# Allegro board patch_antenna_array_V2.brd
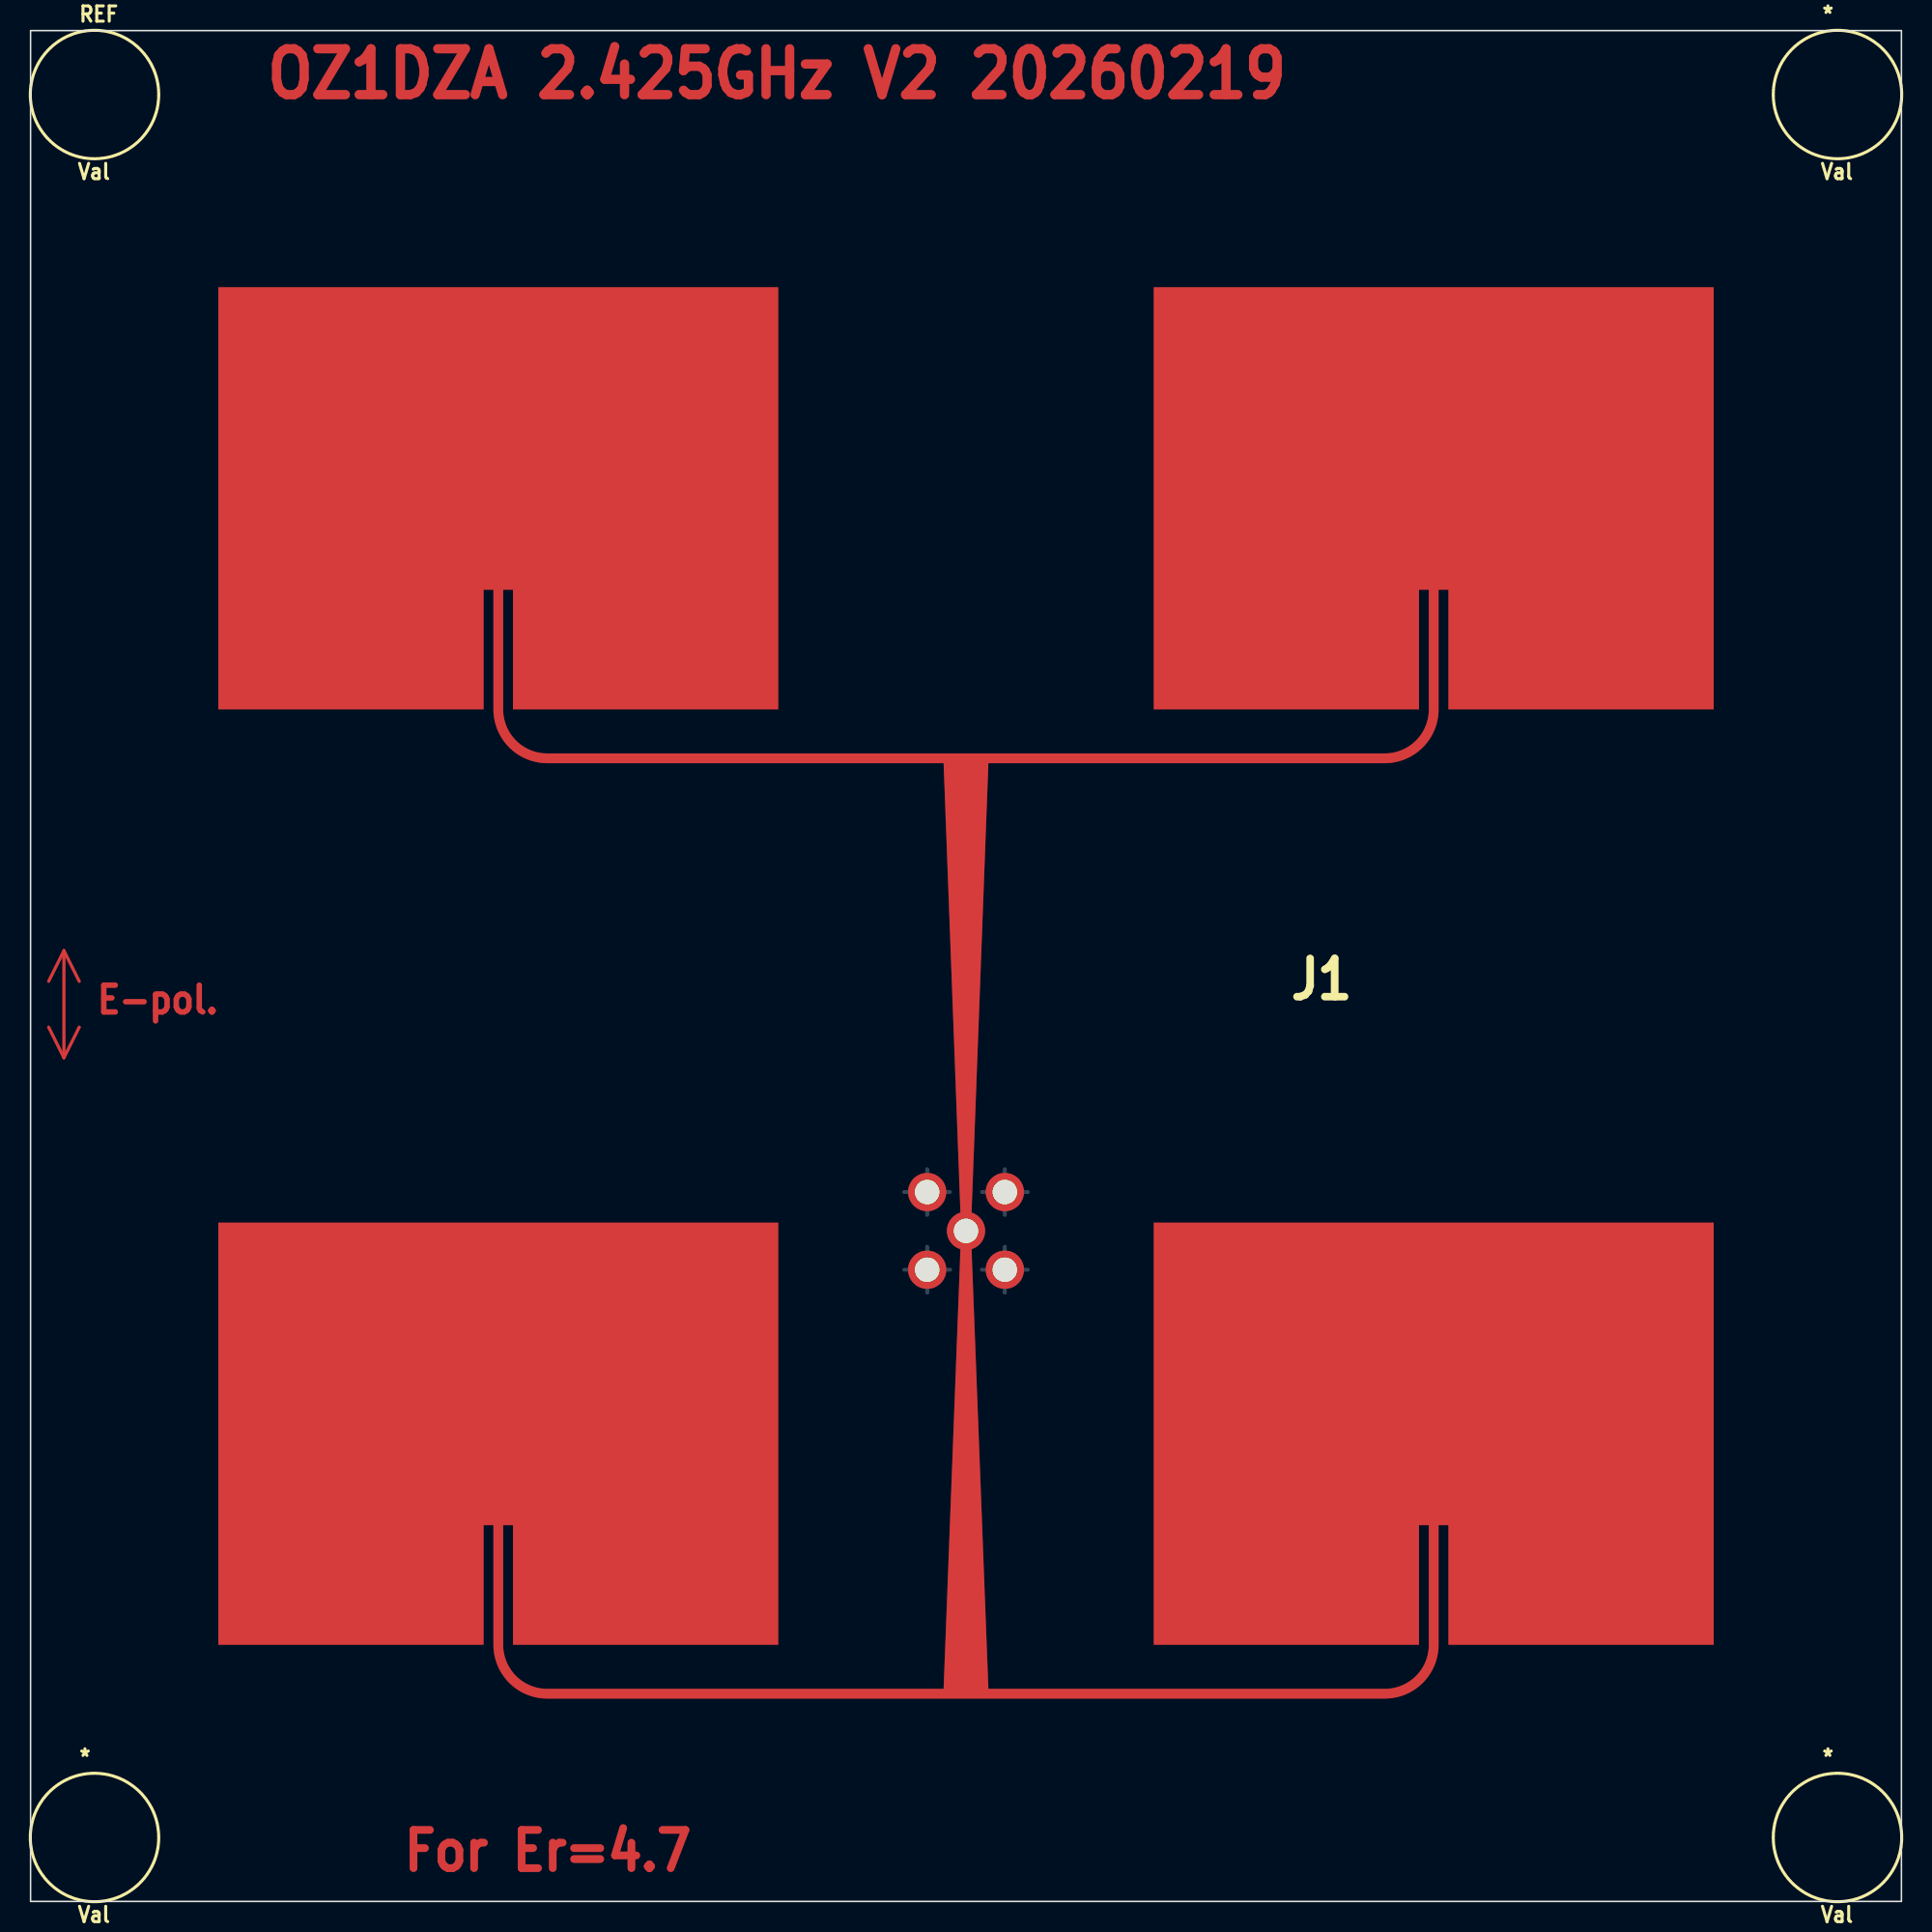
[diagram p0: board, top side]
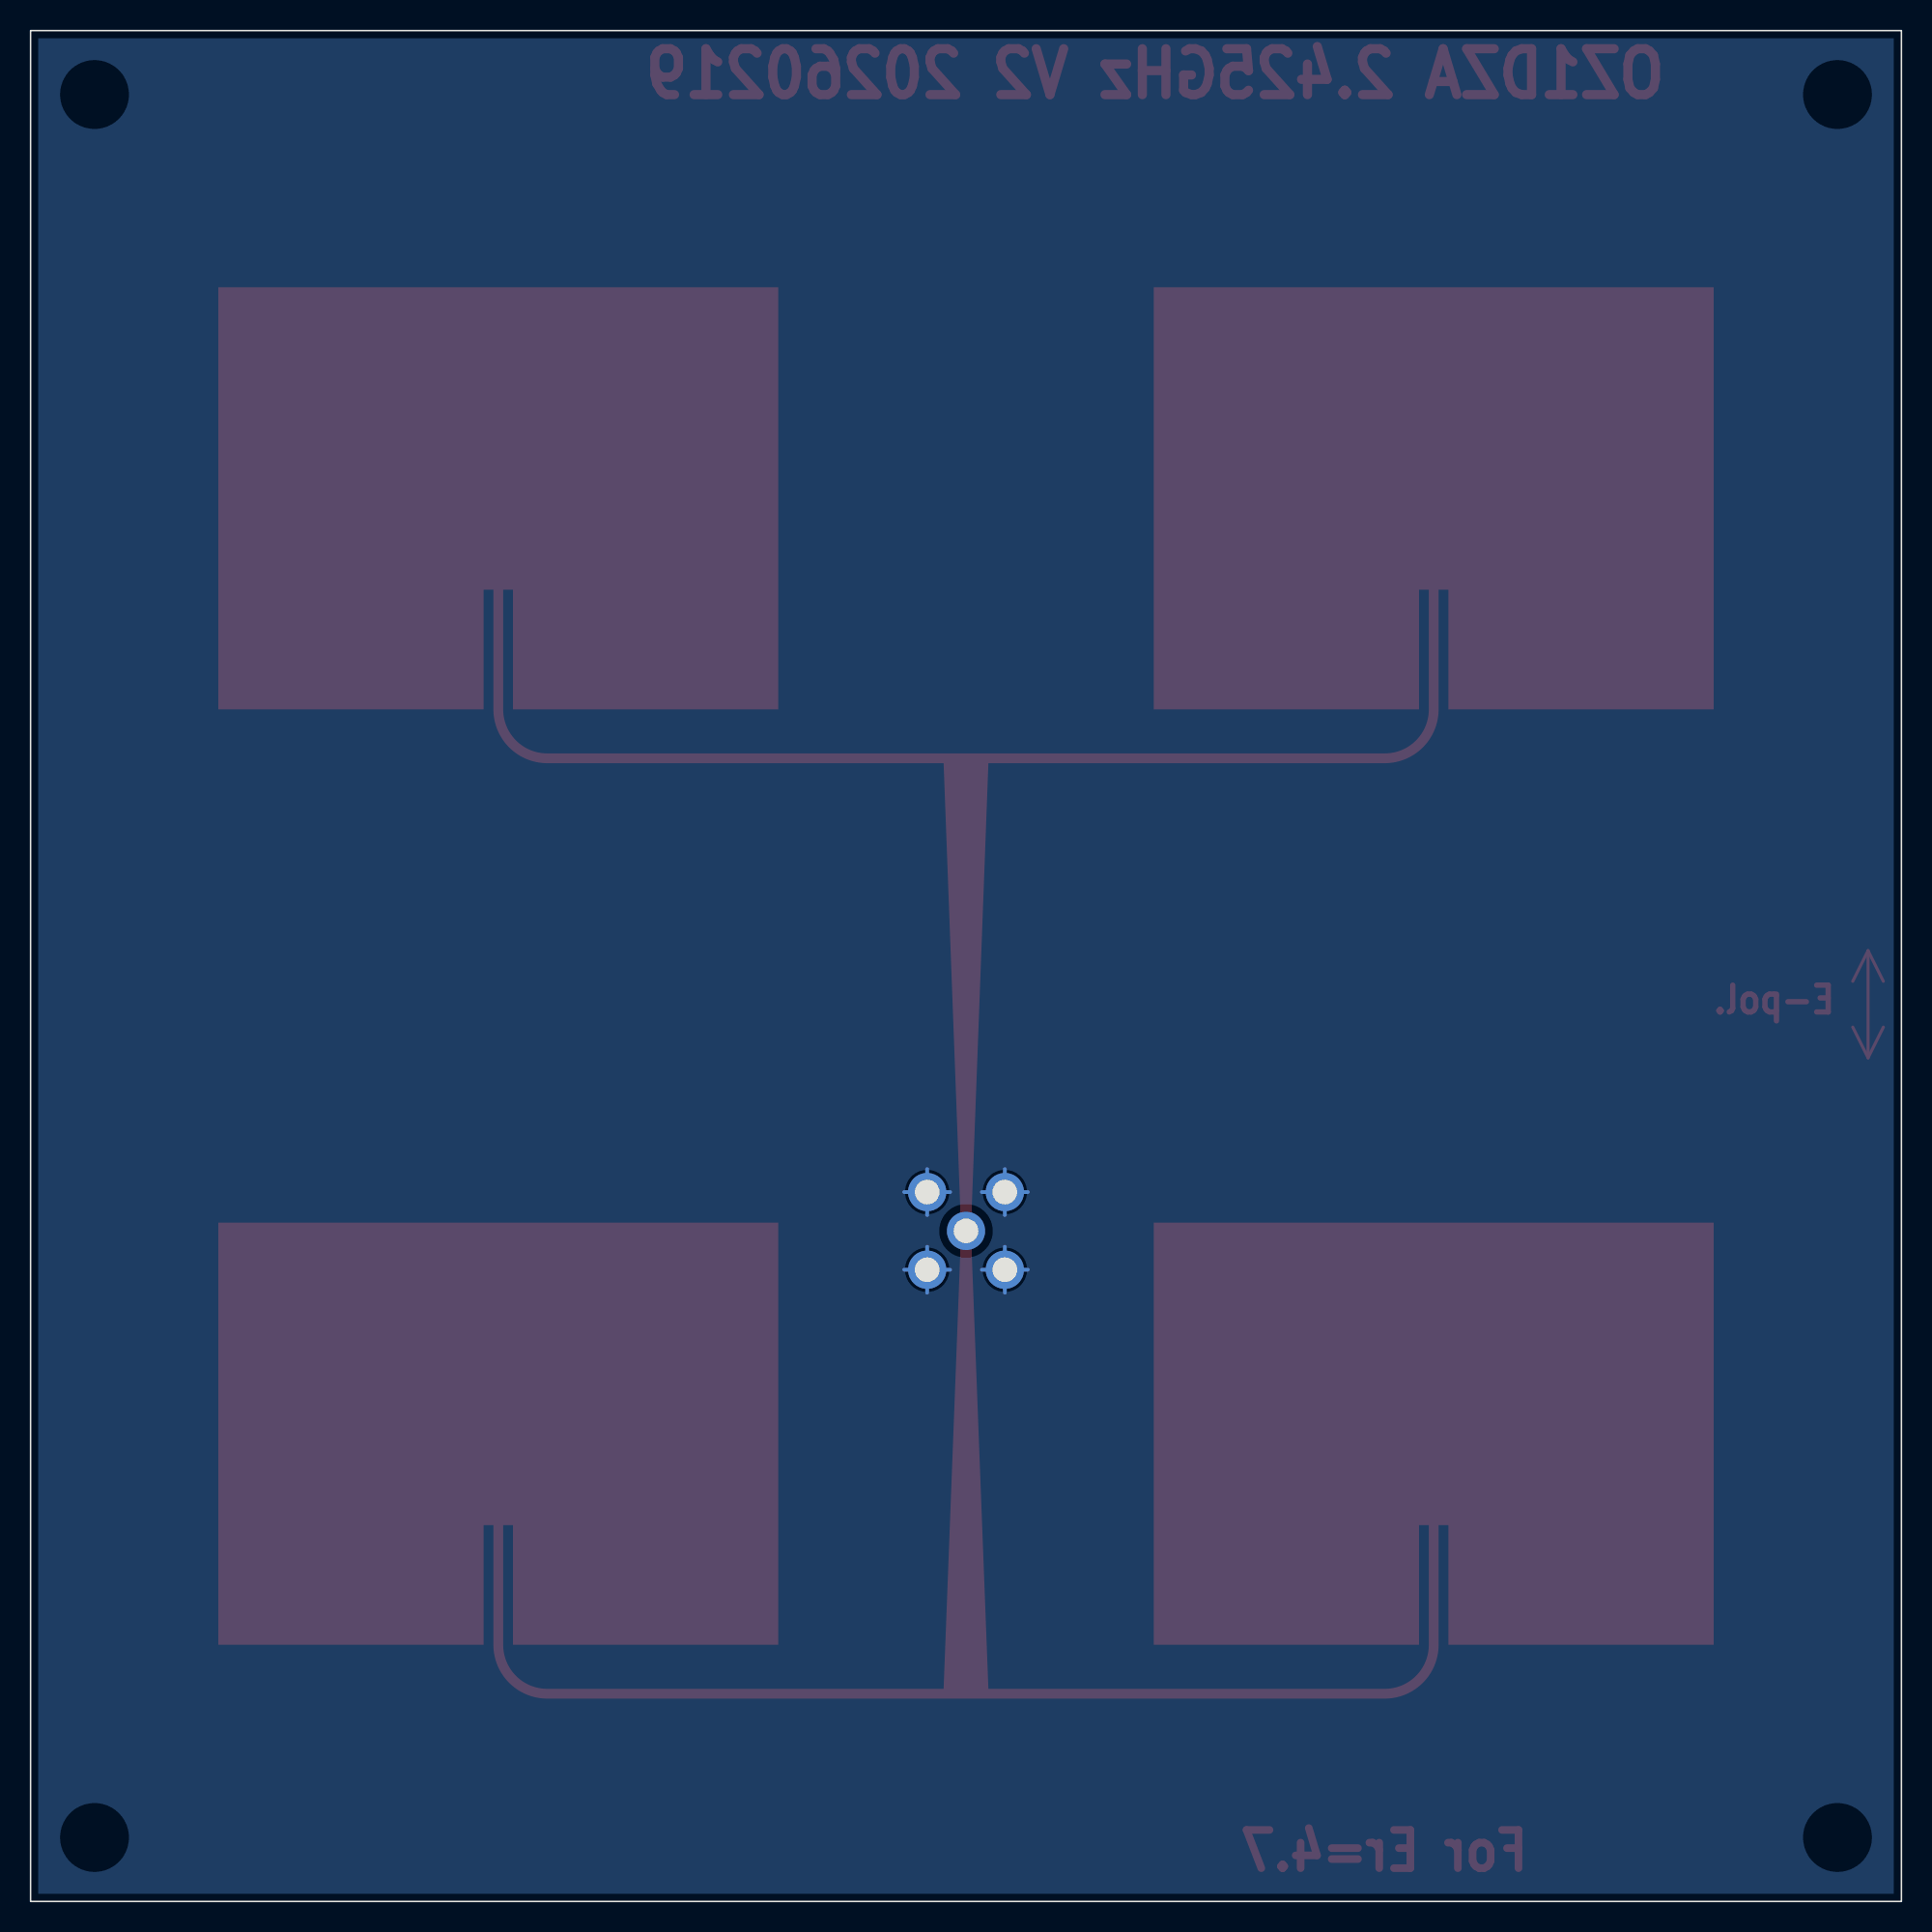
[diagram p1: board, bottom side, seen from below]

Outline 122.36 x 122.36 mm; copper layers: TOP, BOTTOM. Coordinates in mm from the lower left corner of the outline.
Outline path: rectangle 0,0 122.36,122.36

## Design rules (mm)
constraint set DEFAULT: min track width 0.3

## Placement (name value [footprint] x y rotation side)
J1  patch_antenna_array  [PATCH_ANTENNA_ARRAY]  61.18 61.18 0 top
NOREF  -  [#2]  0 0 0 top
NOREF#2  -  [#2]  122.36 0 90 top
REF  Val  [unnamed]  4.18 118.18 0 top
UNK*  Val  [unnamed]  118.18 118.18 0 top
UNK*#2  Val  [unnamed]  4.18 4.18 0 top
UNK*#3  Val  [unnamed]  118.18 4.18 0 top

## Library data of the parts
J1 = CON5

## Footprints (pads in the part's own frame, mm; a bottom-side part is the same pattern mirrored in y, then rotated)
PATCH_ANTENNA_ARRAY
  round 2.5 hole 1.6: 1(0,-17.325) 2(2.54,-14.785) 3(-2.54,-14.785) 4(-2.54,-19.865) 5(2.54,-19.865)
unnamed
  round 0 hole 3.5 unplated: (0,0)

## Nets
GND: J1.2 J1.3 J1.4 J1.5

Pads without a net: J1 1

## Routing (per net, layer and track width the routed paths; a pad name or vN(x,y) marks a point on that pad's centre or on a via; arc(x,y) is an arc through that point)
GND: length 24
  BOTTOM w0.25: 62.22,41.32 J1.5 ; J1.5 65.22,41.32 ; J1.5 63.72,39.82 ; J1.5 63.72,42.82 ; 63.72,44.9 J1.2 ; J1.2 62.22,46.4 ; J1.2 65.22,46.4 ; J1.2 63.72,47.9 ; J1.3 58.64,47.9 ; J1.3 58.64,44.9 ; J1.3 57.14,46.4 ; J1.3 60.14,46.4 ; J1.4 60.14,41.32 ; J1.4 57.14,41.32 ; J1.4 58.64,42.82 ; J1.4 58.64,39.82

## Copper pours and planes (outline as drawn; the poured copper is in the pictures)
GND on BOTTOM: 0,122.36 0,0 122.36,0 122.36,122.36
Net_7 on TOP (solid shape): 48.9,77.97 31.55,77.97 31.55,85.79 30.91,85.79 30.91,77.97 31.75,75.93 33.79,75.09 88.57,75.09 90.61,75.93 91.45,77.97 91.45,85.79 90.81,85.79 90.81,77.97 73.46,77.97 73.46,105.58 110.08,105.58 110.08,77.97 92.73,77.97 92.73,85.79 92.09,85.79 92.09,77.97 91.06,75.48 88.57,74.45 62.65,74.45 61.51,44.18 62.14,44.18 62.14,43.54 61.51,43.54 62.65,13.91 88.57,13.91 90.61,14.75 91.45,16.79 91.45,24.61 90.81,24.61 90.81,16.79 73.46,16.79 73.46,44.4 110.08,44.4 110.08,16.79 92.73,16.79 92.73,24.61 92.09,24.61 92.09,16.79 91.06,14.3 88.57,13.27 33.79,13.27 31.3,14.3 30.27,16.79 30.27,24.61 29.63,24.61 29.63,16.79 12.28,16.79 12.28,44.4 48.9,44.4 48.9,16.79 31.55,16.79 31.55,24.61 30.91,24.61 30.91,16.79 31.75,14.75 33.79,13.91 59.72,13.91 60.86,43.86 59.72,74.45 33.79,74.45 31.3,75.48 30.27,77.97 30.27,85.79 29.63,85.79 29.63,77.97 12.28,77.97 12.28,105.58 48.9,105.58

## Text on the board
TOP: E-pol. | For Er=4.7 | OZ1DZA 2.425GHz V2 20260219
